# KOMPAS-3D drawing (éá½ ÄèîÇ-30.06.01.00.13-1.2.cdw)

Views: Вид 1, Вид 2, Вид 3
Referenced files: Вал.cdw
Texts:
  Вал
  Андрей
  Noncommercial version
  Ra0.8
  Ra3.2
  R 0,5 max
  Ra6.3
  2. H14, h14,    IT14 2 .
  3. * Размер обеспечить инструментом.
  Сталь 40Х ГОСТ 4543-71
  ДГТУ
  ОКМА-30.06.01.00.13-
Dimensions and other numbers on the sheet: 165; 53; 6; 100; 150; 60; 110; 490; 120; 135; 0,0023; 0,004; 125; 108; 32; 95; 28; 0,022; 2,5; 4 фаски; 1,6; 16; 14; 0,002; 0,086; 2; 1; 0,5; 1. 38...42 HRC Э; 1:2; 5; 0,84; 0; 3; 4; 7; 8; 9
